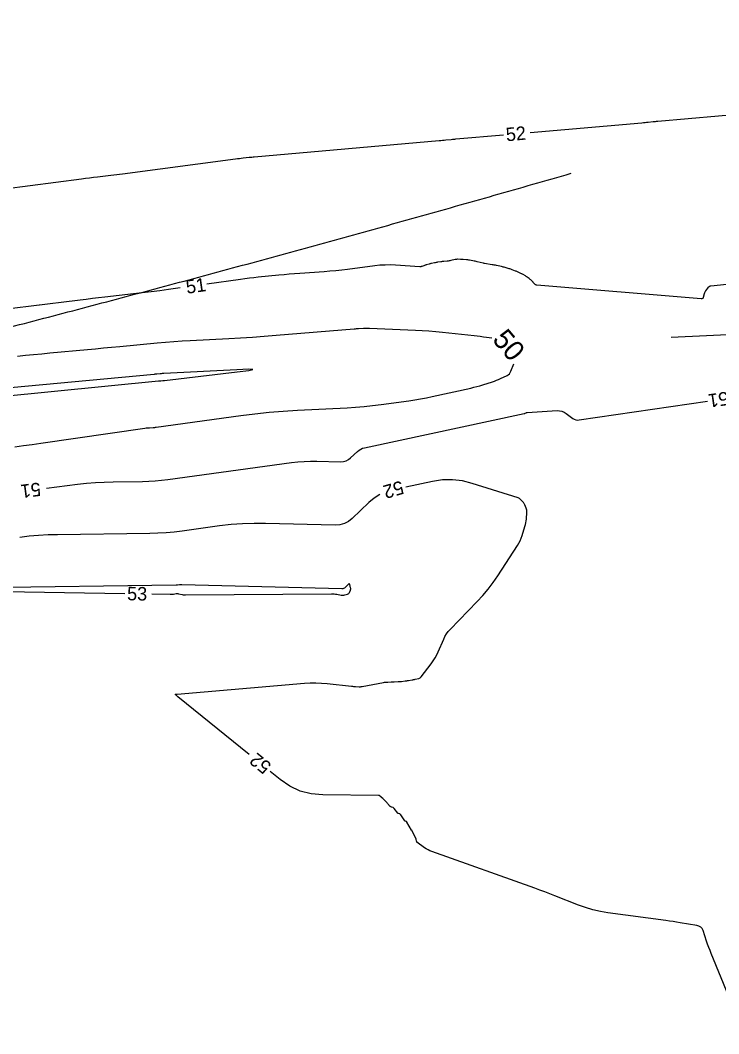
# Model space of a CAD drawing. Extents: x 2384780 to 2405861, y 547869 to 573706.
# Drawn here: x 2391091.5 to 2391194.9, y 552466.2 to 552616.3 of the extents above; entities that cross this region are included whole.
import ezdxf

# ---------------------------------------------------------------- set-up
doc = ezdxf.new("R2010")
doc.units = 0
for name, color, linetype in [('Breaklines', 7, 'Continuous'), ('Old_Level_60', 7, 'Continuous'), ('Old_Level_61', 7, 'Continuous'), ('Old_Level_62', 7, 'Continuous'), ('Old_Level_63', 7, 'Continuous')]:
    doc.layers.add(name, color=color, linetype=linetype)

msp = doc.modelspace()

# ---------------------------------------------------------------- linework, layer by layer
at = {"layer": 'Breaklines'}
msp.add_line((2391187.86623, 552569.40718), (2391317.54475, 552575.63548), dxfattribs=at)
at = {"layer": 'Old_Level_60'}
for points in [[(2391167.00425, 552599.72625), (2391183.54075, 552601.17425), (2391183.773, 552601.195), (2391184.00525, 552601.21675), (2391184.2375, 552601.23925), (2391184.4695, 552601.26275), (2391185.2275, 552601.34075), (2391185.39, 552601.35725), (2391185.5525, 552601.373), (2391185.715, 552601.388), (2391185.87775, 552601.40275), (2391203.85525, 552602.977)], [(2391081.4925, 552590.38025), (2391100.51075, 552592.86525), (2391101.114, 552592.94275), (2391101.71725, 552593.01775), (2391102.321, 552593.09025), (2391102.925, 552593.16025), (2391104.8985, 552593.385), (2391105.32125, 552593.43425), (2391105.744, 552593.48525), (2391106.16625, 552593.53825), (2391106.58825, 552593.59325), (2391123.366, 552595.8175), (2391123.6395, 552595.853), (2391123.9135, 552595.88675), (2391124.1875, 552595.91875), (2391124.462, 552595.949), (2391125.35825, 552596.045), (2391125.5505, 552596.06525), (2391125.74275, 552596.08425), (2391125.935, 552596.1025), (2391126.1275, 552596.12), (2391153.5115, 552598.518), (2391153.7585, 552598.54), (2391154.00525, 552598.56325), (2391154.25175, 552598.58725), (2391154.49825, 552598.61225), (2391155.3035, 552598.696), (2391155.476, 552598.7135), (2391155.64875, 552598.73025), (2391155.82125, 552598.7465), (2391155.99425, 552598.762), (2391163.0195, 552599.37725)], [(2391164.82825, 552579.198), (2391164.32225, 552579.38925), (2391164.2135, 552579.42925), (2391164.104, 552579.467), (2391163.99375, 552579.50275), (2391163.88275, 552579.53625), (2391163.2715, 552579.71525), (2391163.14025, 552579.7525), (2391163.00825, 552579.7875), (2391162.87575, 552579.82), (2391162.74275, 552579.8505), (2391161.9955, 552580.01425), (2391161.835, 552580.04825), (2391161.67425, 552580.08), (2391161.513, 552580.10925), (2391161.35125, 552580.136), (2391160.23475, 552580.3135), (2391160.2155, 552580.31675), (2391160.1965, 552580.321), (2391160.17775, 552580.32575), (2391160.15925, 552580.331), (2391160.0985, 552580.35), (2391160.0855, 552580.35375), (2391160.0725, 552580.3575), (2391160.05925, 552580.361), (2391160.04625, 552580.36425), (2391159.151, 552580.5795), (2391158.99425, 552580.61575), (2391158.837, 552580.64925), (2391158.67925, 552580.68), (2391158.521, 552580.70825), (2391158.00275, 552580.79575), (2391157.89175, 552580.8135), (2391157.78025, 552580.82925), (2391157.6685, 552580.843), (2391157.5565, 552580.8545), (2391157.0745, 552580.90025), (2391156.971, 552580.909), (2391156.8675, 552580.916), (2391156.764, 552580.92075), (2391156.66025, 552580.92375), (2391156.2495, 552580.93175), (2391156.16175, 552580.931), (2391156.0745, 552580.925), (2391155.98775, 552580.9135), (2391155.90175, 552580.89725), (2391155.25, 552580.7525), (2391155.11, 552580.72375), (2391154.96925, 552580.69925), (2391154.82775, 552580.6795), (2391154.68575, 552580.66375), (2391154.18, 552580.6165), (2391154.0715, 552580.6055), (2391153.9635, 552580.593), (2391153.8555, 552580.57875), (2391153.748, 552580.56275), (2391153.2535, 552580.48575), (2391153.1475, 552580.4685), (2391153.042, 552580.4495), (2391152.93675, 552580.42875), (2391152.832, 552580.4065), (2391152.388, 552580.30875), (2391152.29325, 552580.28725), (2391152.1985, 552580.264), (2391152.1045, 552580.2395), (2391152.0105, 552580.2135), (2391151.6005, 552580.0965), (2391151.513, 552580.071), (2391151.42575, 552580.044), (2391151.33875, 552580.0155), (2391151.2525, 552579.986), (2391150.92125, 552579.86975), (2391150.84975, 552579.8485), (2391150.77725, 552579.83475), (2391150.7035, 552579.82825), (2391150.629, 552579.8295), (2391147.04175, 552580.06025), (2391146.27375, 552580.09125), (2391145.507, 552580.085), (2391144.74125, 552580.04175), (2391143.97675, 552579.9615), (2391139.93625, 552579.4385), (2391139.06975, 552579.33275), (2391138.202, 552579.2395), (2391137.333, 552579.15925), (2391136.46275, 552579.0915), (2391132.853, 552578.83725), (2391132.07975, 552578.78), (2391131.307, 552578.71675), (2391130.5345, 552578.6475), (2391129.76275, 552578.57225), (2391126.70825, 552578.26325), (2391126.054, 552578.19375), (2391125.4005, 552578.11825), (2391124.748, 552578.03625), (2391124.096, 552577.94775), (2391119.10575, 552577.247)], [(2391203.67625, 552577.96475), (2391193.766, 552576.967), (2391193.61425, 552576.9365), (2391193.47925, 552576.877), (2391193.36125, 552576.78875), (2391193.26, 552576.67175), (2391192.9565, 552576.2425), (2391192.89625, 552576.14825), (2391192.84525, 552576.04975), (2391192.80375, 552575.947), (2391192.7715, 552575.84), (2391192.63225, 552575.28675), (2391192.59075, 552575.18425), (2391192.5265, 552575.114), (2391192.43925, 552575.076), (2391192.32875, 552575.07), (2391167.973, 552577.09725), (2391167.88925, 552577.11175), (2391167.813, 552577.14125), (2391167.74425, 552577.1855), (2391167.683, 552577.24475), (2391167.495, 552577.46175), (2391167.45425, 552577.50775), (2391167.412, 552577.5525), (2391167.36875, 552577.59625), (2391167.32425, 552577.6385), (2391167.0685, 552577.87575), (2391167.013, 552577.92575), (2391166.95625, 552577.97425), (2391166.89825, 552578.02125), (2391166.839, 552578.067), (2391166.54475, 552578.28725), (2391166.48125, 552578.3335), (2391166.4165, 552578.378), (2391166.3505, 552578.421), (2391166.28325, 552578.46225), (2391165.92925, 552578.673), (2391165.853, 552578.71725), (2391165.77575, 552578.75975), (2391165.6975, 552578.80025), (2391165.61825, 552578.83925), (2391165.1965, 552579.04075), (2391165.10575, 552579.083), (2391165.014, 552579.12325), (2391164.92175, 552579.1615), (2391164.82825, 552579.198)], [(2391115.1445, 552576.69075), (2391113.4245, 552576.44925), (2391112.12675, 552576.27175), (2391110.82825, 552576.10325), (2391109.52825, 552575.944), (2391108.22725, 552575.79375), (2391103.9755, 552575.318), (2391103.0645, 552575.21475), (2391102.154, 552575.10875), (2391101.24375, 552575.00025), (2391100.33375, 552574.889), (2391088.17025, 552573.38525)], [(2391088.56125, 552560.60975), (2391111.9285, 552562.91), (2391112.01625, 552562.918), (2391112.10425, 552562.925), (2391112.19225, 552562.931), (2391112.28025, 552562.936), (2391112.56775, 552562.95), (2391112.6295, 552562.9535), (2391112.691, 552562.95825), (2391112.7525, 552562.964), (2391112.81375, 552562.97075), (2391123.586, 552564.249), (2391125.3155, 552564.474), (2391125.88775, 552564.60075), (2391125.3025, 552564.6295), (2391123.5595, 552564.56025), (2391112.7485, 552564.00925), (2391112.6035, 552564.00125), (2391112.4585, 552563.99125), (2391112.31375, 552563.98), (2391112.169, 552563.967), (2391111.69675, 552563.92175), (2391111.5955, 552563.912), (2391111.49425, 552563.9025), (2391111.393, 552563.893), (2391111.29175, 552563.8835), (2391085.192, 552561.43925)], [(2391095.35025, 552547.00225), (2391099.94075, 552547.59525), (2391101.262, 552547.7465), (2391102.586, 552547.85975), (2391103.91275, 552547.9345), (2391105.24225, 552547.971), (2391109.5895, 552548.02775), (2391110.51975, 552548.054), (2391111.44825, 552548.109), (2391112.3745, 552548.19225), (2391113.2985, 552548.304), (2391131.66125, 552550.81075), (2391132.59225, 552550.919), (2391133.5255, 552550.98975), (2391134.46075, 552551.02275), (2391135.39825, 552551.0185), (2391138.9165, 552550.93175), (2391139.332, 552550.9595), (2391139.718, 552551.0645), (2391140.074, 552551.2465), (2391140.40025, 552551.5055), (2391141.4175, 552552.47775), (2391141.645, 552552.66775), (2391141.89175, 552552.82175), (2391142.15775, 552552.93925), (2391142.443, 552553.0205), (2391166.1105, 552558.08875), (2391166.11875, 552558.0905), (2391166.127, 552558.092), (2391166.135, 552558.09325), (2391166.14325, 552558.0945), (2391166.172, 552558.0985), (2391166.177, 552558.099), (2391166.182, 552558.1), (2391166.187, 552558.101), (2391166.19175, 552558.102), (2391166.20925, 552558.10575), (2391166.212, 552558.10675), (2391166.21425, 552558.108), (2391166.21625, 552558.11), (2391166.218, 552558.11225), (2391166.22275, 552558.1205), (2391166.224, 552558.122), (2391166.22525, 552558.1235), (2391166.227, 552558.1245), (2391166.22875, 552558.1255), (2391166.40275, 552558.2), (2391166.4405, 552558.2145), (2391166.479, 552558.22525), (2391166.51825, 552558.233), (2391166.55825, 552558.23725), (2391170.9715, 552558.5115), (2391171.3355, 552558.5035), (2391171.6805, 552558.433), (2391172.00675, 552558.30025), (2391172.314, 552558.10525), (2391173.28725, 552557.36575), (2391173.502, 552557.232), (2391173.7295, 552557.147), (2391173.9695, 552557.11125), (2391174.2225, 552557.1245), (2391193.24075, 552559.90225)], [(2391165.98725, 552544.8945), (2391165.60175, 552545.316), (2391165.515, 552545.39975), (2391165.4195, 552545.47), (2391165.31575, 552545.52725), (2391165.20325, 552545.571), (2391158.41125, 552547.7335), (2391156.951, 552548.099), (2391155.48125, 552548.26875), (2391154.002, 552548.24275), (2391152.51325, 552548.02075), (2391148.566, 552547.1755)], [(2391144.73725, 552546.0695), (2391143.89425, 552545.544), (2391143.10425, 552544.884), (2391140.633, 552542.52225), (2391140.078, 552542.08175), (2391139.4725, 552541.77225), (2391138.81625, 552541.59375), (2391138.10925, 552541.54625), (2391127.8005, 552541.8005), (2391126.089, 552541.8085), (2391124.3815, 552541.748), (2391122.67775, 552541.619), (2391120.97775, 552541.4215), (2391115.4305, 552540.66425), (2391114.2405, 552540.52025), (2391113.04775, 552540.413), (2391111.85225, 552540.34225), (2391110.654, 552540.30825), (2391096.99425, 552540.13), (2391095.5865, 552540.0915), (2391094.18175, 552540.01225), (2391092.77975, 552539.8925), (2391091.38075, 552539.73225)], [(2391125.35675, 552507.56875), (2391114.8205, 552516.119), (2391114.771, 552516.1595), (2391114.7215, 552516.2), (2391114.672, 552516.2405), (2391114.62275, 552516.2815), (2391114.458, 552516.41825), (2391114.43475, 552516.4425), (2391114.43, 552516.46175), (2391114.444, 552516.47575), (2391114.47625, 552516.4845), (2391114.66075, 552516.51225), (2391114.66575, 552516.51275), (2391114.67075, 552516.51275), (2391114.6755, 552516.51225), (2391114.6805, 552516.51125), (2391114.69625, 552516.5075), (2391114.69975, 552516.50675), (2391114.703, 552516.5065), (2391114.7065, 552516.50625), (2391114.71, 552516.5065), (2391133.58475, 552518.11825), (2391134.42025, 552518.1695), (2391135.255, 552518.18), (2391136.0895, 552518.14975), (2391136.92325, 552518.07925), (2391140.50025, 552517.689), (2391140.65725, 552517.67275), (2391140.81425, 552517.65875), (2391140.9715, 552517.6465), (2391141.12875, 552517.63625), (2391141.643, 552517.606), (2391141.753, 552517.60275), (2391141.8625, 552517.6065), (2391141.97175, 552517.617), (2391142.0805, 552517.63425), (2391145.2605, 552518.237), (2391145.41725, 552518.26325), (2391145.575, 552518.28225), (2391145.73325, 552518.29425), (2391145.89225, 552518.29925), (2391146.41275, 552518.30375), (2391146.52425, 552518.30525), (2391146.63575, 552518.3085), (2391146.747, 552518.31325), (2391146.8585, 552518.3195), (2391147.436, 552518.35525), (2391147.55975, 552518.36375), (2391147.68325, 552518.374), (2391147.8065, 552518.38575), (2391147.92975, 552518.39925), (2391148.478, 552518.463), (2391148.5955, 552518.47725), (2391148.7125, 552518.4935), (2391148.8295, 552518.511), (2391148.94625, 552518.5305), (2391149.4885, 552518.624), (2391149.6045, 552518.64475), (2391149.72025, 552518.667), (2391149.83575, 552518.691), (2391149.95075, 552518.71625), (2391150.47725, 552518.83575), (2391150.58475, 552518.86975), (2391150.6815, 552518.92), (2391150.768, 552518.987), (2391150.84375, 552519.0705), (2391152.327, 552521.00275), (2391152.631, 552521.425), (2391152.907, 552521.86375), (2391153.15525, 552522.31875), (2391153.3755, 552522.79), (2391154.1805, 552524.66025), (2391154.36925, 552525.05), (2391154.59125, 552525.41775), (2391154.84625, 552525.76325), (2391155.13425, 552526.08675), (2391159.15525, 552530.21375), (2391159.993, 552531.11725), (2391160.783, 552532.0585), (2391161.5255, 552533.038), (2391162.2205, 552534.05525), (2391165.10025, 552538.503), (2391165.3155, 552538.862), (2391165.50425, 552539.233), (2391165.66675, 552539.6165), (2391165.80275, 552540.012), (2391166.21025, 552541.34475), (2391166.286, 552541.61725), (2391166.347, 552541.893), (2391166.3935, 552542.17125), (2391166.42525, 552542.4525), (2391166.51275, 552543.4595), (2391166.517, 552543.614), (2391166.50275, 552543.7655), (2391166.46975, 552543.914), (2391166.4185, 552544.05975), (2391166.22, 552544.531), (2391166.1735, 552544.62925), (2391166.11925, 552544.72275), (2391166.05725, 552544.811), (2391165.98725, 552544.8945)], [(2391110.93, 552531.35125), (2391113.6725, 552531.3045), (2391113.796, 552531.305), (2391113.91925, 552531.3105), (2391114.042, 552531.32125), (2391114.16475, 552531.337), (2391114.5645, 552531.397), (2391114.65, 552531.4055), (2391114.735, 552531.406), (2391114.81975, 552531.398), (2391114.90425, 552531.38175), (2391115.4555, 552531.24825), (2391115.57425, 552531.2235), (2391115.6935, 552531.206), (2391115.814, 552531.19575), (2391115.935, 552531.193), (2391137.56725, 552531.3615), (2391137.7645, 552531.3585), (2391137.96075, 552531.34625), (2391138.15625, 552531.325), (2391138.351, 552531.29475), (2391138.98925, 552531.18), (2391139.12325, 552531.16375), (2391139.2565, 552531.1635), (2391139.38875, 552531.179), (2391139.52025, 552531.2105), (2391139.94775, 552531.33875), (2391140.033, 552531.37375), (2391140.10475, 552531.42375), (2391140.1635, 552531.48875), (2391140.209, 552531.56875), (2391140.36725, 552531.924), (2391140.39475, 552532.00075), (2391140.4085, 552532.07875), (2391140.40925, 552532.158), (2391140.39675, 552532.23825), (2391140.28125, 552532.72475), (2391140.25, 552532.80675), (2391140.2055, 552532.844), (2391140.14775, 552532.83675), (2391140.077, 552532.78525), (2391139.58225, 552532.31225), (2391139.47125, 552532.22425), (2391139.35, 552532.16225), (2391139.2185, 552532.1265), (2391139.077, 552532.117), (2391115.3995, 552532.701), (2391115.313, 552532.7015), (2391115.22675, 552532.6985), (2391115.1405, 552532.69175), (2391115.05475, 552532.682), (2391114.77425, 552532.6435), (2391114.714, 552532.63625), (2391114.65375, 552532.631), (2391114.59325, 552532.62725), (2391114.53275, 552532.6255), (2391085.82275, 552532.251)], [(2391086.08875, 552531.774), (2391106.9305, 552531.41925)], [(2391147.3705, 552498.8875), (2391146.8555, 552499.56275), (2391146.811, 552499.613), (2391146.76025, 552499.65425), (2391146.7035, 552499.68675), (2391146.64075, 552499.7105), (2391146.42575, 552499.7735), (2391146.38125, 552499.78975), (2391146.3405, 552499.81175), (2391146.30325, 552499.83925), (2391146.2695, 552499.87225), (2391145.88, 552500.3075), (2391145.812, 552500.38275), (2391145.7435, 552500.457), (2391145.674, 552500.5305), (2391145.60375, 552500.6035), (2391145.37325, 552500.84025), (2391145.3235, 552500.8905), (2391145.273, 552500.94025), (2391145.22175, 552500.989), (2391145.17, 552501.03725), (2391144.9815, 552501.2095), (2391144.942, 552501.245), (2391144.90125, 552501.27925), (2391144.86, 552501.31275), (2391144.81775, 552501.34525), (2391144.67875, 552501.44975), (2391144.648, 552501.46925), (2391144.61525, 552501.4835), (2391144.58075, 552501.492), (2391144.5445, 552501.495), (2391136.2655, 552501.56525), (2391134.541, 552501.71825), (2391132.9155, 552502.14675), (2391131.38925, 552502.85125), (2391129.96225, 552503.83125), (2391128.4625, 552505.04825)], [(2391198.70325, 552466.1855), (2391193.814, 552478.06075), (2391193.62825, 552478.52225), (2391193.44975, 552478.9865), (2391193.2785, 552479.4535), (2391193.1145, 552479.92325), (2391192.59075, 552481.46225), (2391192.4495, 552481.75775), (2391192.25025, 552481.98475), (2391191.99325, 552482.14325), (2391191.67825, 552482.233), (2391189.209, 552482.6315), (2391188.67975, 552482.71525), (2391188.14975, 552482.79575), (2391187.6195, 552482.873), (2391187.0885, 552482.94675), (2391178.50325, 552484.11475), (2391177.38325, 552484.30125), (2391176.28025, 552484.554), (2391175.1945, 552484.8725), (2391174.126, 552485.257), (2391170.6635, 552486.62075), (2391169.9205, 552486.91), (2391169.175, 552487.19275), (2391168.42725, 552487.4695), (2391167.67725, 552487.74), (2391152.418, 552493.169), (2391152.13675, 552493.2805), (2391151.866, 552493.41125), (2391151.60525, 552493.56125), (2391151.35475, 552493.73075), (2391150.218, 552494.5605), (2391150.21425, 552494.56375), (2391150.21125, 552494.5675), (2391150.209, 552494.57175), (2391150.2075, 552494.5765), (2391150.20375, 552494.59275), (2391150.203, 552494.59625), (2391150.202, 552494.59975), (2391150.20125, 552494.60325), (2391150.2005, 552494.6065), (2391150.193, 552494.638), (2391150.1915, 552494.64475), (2391150.18975, 552494.65125), (2391150.18825, 552494.658), (2391150.18675, 552494.66475), (2391150.1725, 552494.72325), (2391150.1695, 552494.73575), (2391150.1665, 552494.74825), (2391150.1635, 552494.761), (2391150.1605, 552494.7735), (2391150.1145, 552494.9675), (2391150.1135, 552494.97225), (2391150.11225, 552494.977), (2391150.11125, 552494.98175), (2391150.11025, 552494.98675), (2391150.10675, 552495.0025), (2391150.106, 552495.00575), (2391150.105, 552495.009), (2391150.10375, 552495.01225), (2391150.10225, 552495.0155), (2391149.52975, 552496.25925), (2391149.52125, 552496.2735), (2391149.5105, 552496.28475), (2391149.4975, 552496.293), (2391149.482, 552496.29825), (2391149.42725, 552496.311), (2391149.4165, 552496.31475), (2391149.407, 552496.32025), (2391149.399, 552496.328), (2391149.39225, 552496.3375), (2391148.71975, 552497.55625), (2391148.7, 552497.58525), (2391148.67575, 552497.6085), (2391148.647, 552497.626), (2391148.61375, 552497.63775), (2391148.4985, 552497.6665), (2391148.475, 552497.6745), (2391148.45425, 552497.6865), (2391148.43625, 552497.702), (2391148.421, 552497.7215), (2391147.81975, 552498.64375), (2391147.78775, 552498.685), (2391147.75, 552498.71825), (2391147.70675, 552498.744), (2391147.65775, 552498.762), (2391147.4885, 552498.808), (2391147.454, 552498.82025), (2391147.42275, 552498.83775), (2391147.395, 552498.86), (2391147.3705, 552498.8875)]]:
    msp.add_lwpolyline(points, dxfattribs=at)
at = {"layer": 'Old_Level_61'}
for points in [[(2391161.2915, 552569.26675), (2391160.51775, 552569.3625), (2391160.05825, 552569.41875), (2391159.5985, 552569.47375), (2391159.13875, 552569.52725), (2391158.679, 552569.5795), (2391154.00425, 552570.1025), (2391153.00175, 552570.20575), (2391151.998, 552570.2905), (2391150.993, 552570.35725), (2391149.9865, 552570.406), (2391143.2045, 552570.67275), (2391142.976, 552570.67925), (2391142.7475, 552570.681), (2391142.519, 552570.6775), (2391142.2905, 552570.66925), (2391141.54425, 552570.63375), (2391141.38425, 552570.6255), (2391141.2245, 552570.61575), (2391141.06475, 552570.6045), (2391140.90525, 552570.592), (2391129.3455, 552569.6285), (2391127.60025, 552569.49), (2391125.85375, 552569.36575), (2391124.1065, 552569.2555), (2391122.35825, 552569.15925), (2391116.646, 552568.86825), (2391115.42225, 552568.799), (2391114.19975, 552568.7165), (2391112.978, 552568.62), (2391111.7575, 552568.51025), (2391106.19, 552567.978), (2391104.997, 552567.86425), (2391103.804, 552567.751), (2391102.61075, 552567.6385), (2391101.4175, 552567.5265), (2391095.8365, 552567.00375), (2391094.6405, 552566.8915), (2391093.44475, 552566.77875), (2391092.249, 552566.66525), (2391091.05325, 552566.55125)], [(2391090.67925, 552553.15875), (2391091.949, 552553.33), (2391093.21775, 552553.50625), (2391094.486, 552553.687), (2391109.9355, 552555.92025), (2391110.10125, 552555.94225), (2391110.26725, 552555.96), (2391110.43375, 552555.974), (2391110.6005, 552555.98375), (2391111.14625, 552556.00925), (2391111.263, 552556.01625), (2391111.3795, 552556.0255), (2391111.49575, 552556.03775), (2391111.61175, 552556.0525), (2391124.112, 552557.7895), (2391126.21125, 552558.0575), (2391128.315, 552558.279), (2391130.423, 552558.45375), (2391132.5355, 552558.58225), (2391139.876, 552558.9465), (2391141.1385, 552559.0225), (2391142.39875, 552559.12475), (2391143.65625, 552559.25375), (2391144.9115, 552559.409), (2391149.008, 552559.9595), (2391149.88425, 552560.08675), (2391150.757, 552560.23325), (2391151.62625, 552560.3985), (2391152.49225, 552560.5825), (2391158.1995, 552561.86125), (2391158.64675, 552561.96675), (2391159.09125, 552562.082), (2391159.53325, 552562.20675), (2391159.9725, 552562.3415), (2391161.40325, 552562.797), (2391161.708, 552562.89975), (2391162.0085, 552563.0125), (2391162.30525, 552563.1355), (2391162.598, 552563.26825), (2391163.55925, 552563.7245), (2391163.75, 552563.83675), (2391163.90975, 552563.9775), (2391164.0385, 552564.147), (2391164.1365, 552564.34525), (2391164.5575, 552565.42775)]]:
    msp.add_lwpolyline(points, dxfattribs=at)
at = {"layer": 'Old_Level_62'}
msp.add_spline([(2390750.412, 552493.903), (2390756.0595, 552495.08775), (2390761.7115, 552496.27325), (2390767.3675, 552497.4605), (2390773.02325, 552498.648), (2390778.6805, 552499.8365), (2390784.343, 552501.02675), (2390790.009, 552502.21875), (2390795.6745, 552503.412), (2390801.34075, 552504.6065), (2390807.0125, 552505.8035), (2390812.6885, 552507.00325), (2390818.36375, 552508.2045), (2390824.04125, 552509.40825), (2390829.7205, 552510.6145), (2390835.4035, 552511.8235), (2390841.09, 552513.036), (2390846.77575, 552514.25075), (2390852.464, 552515.46875), (2390858.15625, 552516.69075), (2390863.84925, 552517.91575), (2390869.5415, 552519.144), (2390875.24, 552520.37675), (2390880.94175, 552521.614), (2390886.6405, 552522.8545), (2390892.34075, 552524.099), (2390898.047, 552525.34875), (2390903.7545, 552526.60325), (2390909.46275, 552527.86225), (2390915.17275, 552529.12625), (2390920.8815, 552530.39475), (2390926.5955, 552531.669), (2390932.311, 552532.949), (2390938.0255, 552534.23375), (2390943.74275, 552535.5245), (2390949.463, 552536.8215), (2390955.18475, 552538.12475), (2390960.9055, 552539.43375), (2390966.629, 552540.74925), (2390972.35275, 552542.071), (2390978.07775, 552543.3995), (2390983.80575, 552544.73525), (2390989.53425, 552546.078), (2390995.26325, 552547.42775), (2391000.9935, 552548.78475), (2391006.72375, 552550.14925), (2391012.45675, 552551.5215), (2391018.19, 552552.9015), (2391023.92225, 552554.289), (2391029.659, 552555.6855), (2391035.39375, 552557.08975), (2391041.12925, 552558.50225), (2391046.8685, 552559.92425), (2391052.60575, 552561.3545), (2391058.344, 552562.79375), (2391064.082, 552564.24175), (2391069.822, 552565.6995), (2391075.56175, 552567.1665), (2391081.29975, 552568.64275), (2391087.04225, 552570.12925), (2391092.784, 552571.626), (2391098.5215, 552573.1315), (2391104.26275, 552574.648), (2391110.00625, 552576.1755), (2391115.74525, 552577.7125), (2391121.4855, 552579.2605), (2391127.227, 552580.81975), (2391132.9685, 552582.39), (2391138.7075, 552583.97075), (2391144.44775, 552585.56325), (2391150.18875, 552587.168), (2391155.9255, 552588.783), (2391161.6655, 552590.41075), (2391167.4045, 552592.05075), (2391173.043, 552593.674)], degree=3, dxfattribs=at)
at = {"layer": 'Old_Level_63'}
msp.add_spline([(2390739.62125, 552545.348), (2390745.271, 552546.5335), (2390750.91725, 552547.7185), (2390756.5675, 552548.904), (2390762.221, 552550.09125), (2390767.8725, 552551.2785), (2390773.5255, 552552.467), (2390779.18075, 552553.6565), (2390784.8375, 552554.848), (2390790.49225, 552556.04), (2390796.14925, 552557.234), (2390801.80925, 552558.43025), (2390807.46975, 552559.62825), (2390813.1315, 552560.8285), (2390818.79225, 552562.031), (2390824.45475, 552563.23575), (2390830.117, 552564.443), (2390835.77825, 552565.6525), (2390841.44475, 552566.86575), (2390847.113, 552568.0825), (2390852.7785, 552569.302), (2390858.44025, 552570.5235), (2390864.10825, 552571.7495), (2390869.779, 552572.98025), (2390875.44625, 552574.2135), (2390881.11525, 552575.4515), (2390886.77975, 552576.6925), (2390892.4515, 552577.9385), (2390898.12275, 552579.18975), (2390903.79025, 552580.444), (2390909.46225, 552581.70425), (2390915.13075, 552582.96875), (2390920.80125, 552584.23825), (2390926.47425, 552585.51375), (2390932.143, 552586.794), (2390937.8135, 552588.0795), (2390943.48575, 552589.3715), (2390949.1565, 552590.66875), (2390954.827, 552591.97225), (2390960.5, 552593.28225), (2390966.17, 552594.5985), (2390971.837, 552595.91975), (2390977.51, 552597.24925), (2390983.1815, 552598.5855), (2390988.84775, 552599.9275), (2390994.51775, 552601.27725), (2391000.18725, 552602.6345), (2391005.85475, 552603.9985), (2391011.52375, 552605.37075), (2391017.19125, 552606.7505), (2391022.85825, 552608.138), (2391028.5255, 552609.534), (2391034.19, 552610.9375), (2391039.85525, 552612.34975), (2391045.51975, 552613.7705), (2391051.18175, 552615.1995), (2391056.84525, 552616.63775), (2391062.50425, 552618.08425), (2391068.1655, 552619.54025), (2391073.82775, 552621.0065), (2391079.48125, 552622.48), (2391085.14025, 552623.9645), (2391090.798, 552625.4595), (2391096.44925, 552626.9625), (2391102.10325, 552628.47625), (2391107.75725, 552630.00125), (2391113.40575, 552631.53525), (2391119.05525, 552633.08025), (2391124.703, 552634.636), (2391130.34475, 552636.2015), (2391135.989, 552637.7785), (2391141.63475, 552639.368), (2391147.27575, 552640.968), (2391152.911, 552642.57825), (2391158.5015, 552644.1875)], degree=3, dxfattribs=at)

# ---------------------------------------------------------------- texts
at = {"layer": 'Old_Level_60'}
for s, rotation, p in [('52', 5.0045917, (2391163.4755, 552598.41325)), ('51', 7.9933694, (2391116.1415, 552575.821)), ('51', 188.3096306, (2391196.197, 552561.34475)), ('52', 196.1112556, (2391147.8995, 552548.166)), ('51', 187.3599, (2391094.363, 552547.88325)), ('53', 359.0247306, (2391107.268, 552530.41325)), ('52', 140.9396056, (2391128.80525, 552506.058))]:
    msp.add_text(s, height=2, rotation=rotation, dxfattribs=at).set_placement(p)
at = {"layer": 'Old_Level_61'}
msp.add_text('50', height=3, rotation=310.3904972, dxfattribs=at).set_placement((2391161.2615, 552568.9725))

doc.saveas('drawing.dxf')
